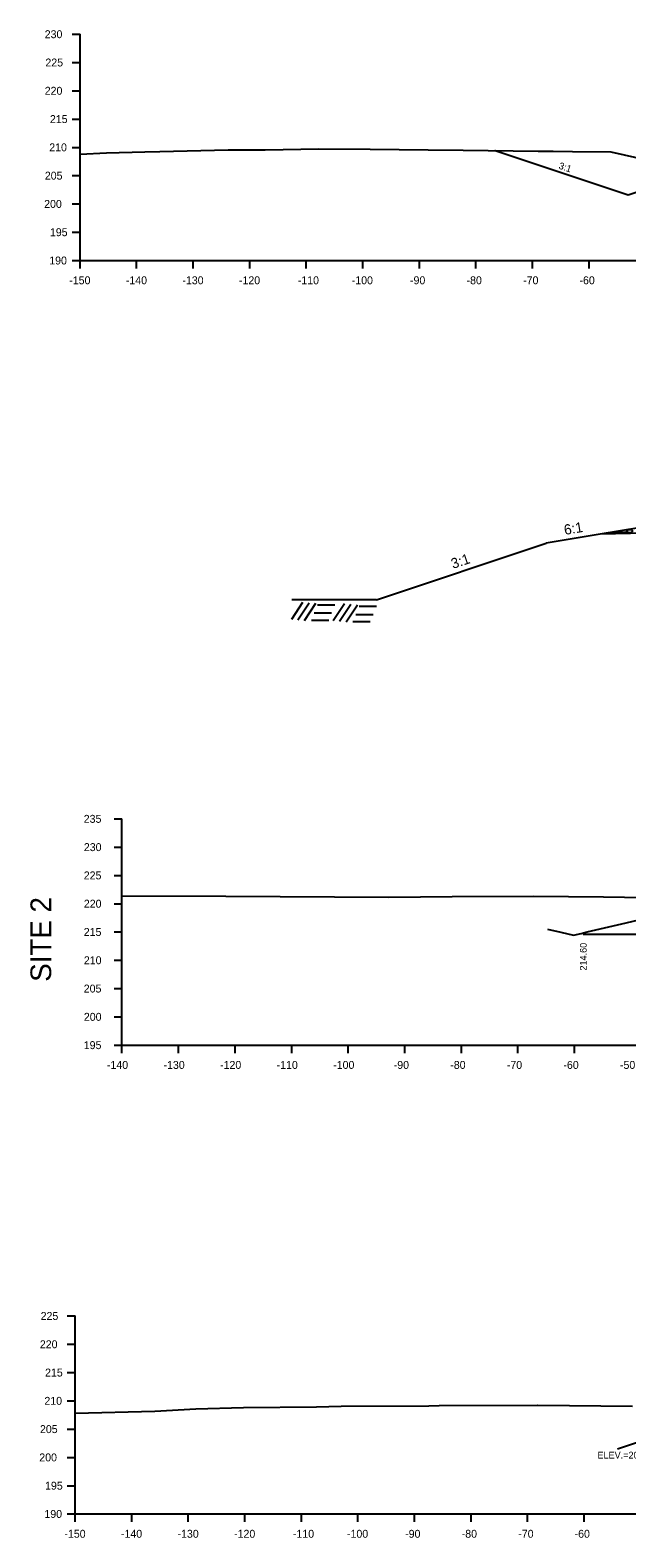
# Model space of a CAD drawing. Extents: x 2829243 to 2838161, y 467639 to 474695.
# Drawn here: x 2831378 to 2831905, y 468841 to 470174 of the extents above; entities that cross this region are included whole.
import ezdxf

# ---------------------------------------------------------------- set-up
doc = ezdxf.new("R2010")
doc.units = 0
for name, color, linetype in [('R_Axis', 7, 'Continuous'), ('R_Axis Annot', 7, 'Continuous'), ('R_Dimension', 7, 'Continuous'), ('R_Draft', 7, 'Continuous'), ('R_Exist Surface', 7, 'Continuous'), ('R_Fin Surface', 7, 'Continuous'), ('R_Grid', 7, 'Continuous'), ('R_Water', 7, 'Continuous'), ('R_Xsect Elev', 7, 'Continuous'), ('R_Xsect Slope', 7, 'Continuous')]:
    doc.layers.add(name, color=color, linetype=linetype)

msp = doc.modelspace()

# ---------------------------------------------------------------- linework, layer by layer
at = {"layer": 'R_Axis'}
for p, q in [((2831415, 470170.3), (2831422, 470170.3)), ((2831422, 469970.3), (2831422, 470170.3)), ((2831415, 470145.3), (2831422, 470145.3)), ((2831415, 470120.3), (2831422, 470120.3)), ((2831415, 470095.3), (2831422, 470095.3)), ((2831415, 470070.3), (2831422, 470070.3)), ((2831415, 470045.3), (2831422, 470045.3)), ((2831415, 470020.3), (2831422, 470020.3)), ((2831415, 469995.3), (2831422, 469995.3)), ((2831415, 469970.3), (2831422, 469970.3)), ((2831422, 469970.3), (2832922, 469970.3)), ((2831422, 469963.3), (2831422, 469970.3)), ((2831472, 469963.3), (2831472, 469970.3)), ((2831522, 469963.3), (2831522, 469970.3)), ((2831572, 469963.3), (2831572, 469970.3)), ((2831622, 469963.3), (2831622, 469970.3)), ((2831672, 469963.3), (2831672, 469970.3)), ((2831722, 469963.3), (2831722, 469970.3)), ((2831772, 469963.3), (2831772, 469970.3)), ((2831822, 469963.3), (2831822, 469970.3)), ((2831872, 469963.3), (2831872, 469970.3)), ((2831452.1, 469476.8), (2831459.1, 469476.8)), ((2831459.1, 469276.8), (2831459.1, 469476.8)), ((2831452.1, 469451.8), (2831459.1, 469451.8)), ((2831452.1, 469426.8), (2831459.1, 469426.8)), ((2831452.1, 469401.8), (2831459.1, 469401.8)), ((2831452.1, 469376.8), (2831459.1, 469376.8)), ((2831452.1, 469351.8), (2831459.1, 469351.8)), ((2831452.1, 469326.8), (2831459.1, 469326.8)), ((2831452.1, 469301.8), (2831459.1, 469301.8)), ((2831452.1, 469276.8), (2831459.1, 469276.8)), ((2831459.1, 469276.8), (2832859.1, 469276.8)), ((2831459.1, 469269.8), (2831459.1, 469276.8)), ((2831509.1, 469269.8), (2831509.1, 469276.8)), ((2831559.1, 469269.8), (2831559.1, 469276.8)), ((2831609.1, 469269.8), (2831609.1, 469276.8)), ((2831659.1, 469269.8), (2831659.1, 469276.8)), ((2831709.1, 469269.8), (2831709.1, 469276.8)), ((2831759.1, 469269.8), (2831759.1, 469276.8)), ((2831809.1, 469269.8), (2831809.1, 469276.8)), ((2831859.1, 469269.8), (2831859.1, 469276.8)), ((2831410.7, 469037.4), (2831417.7, 469037.4)), ((2831417.7, 468862.4), (2831417.7, 469037.4)), ((2831410.7, 469012.4), (2831417.7, 469012.4)), ((2831410.7, 468987.4), (2831417.7, 468987.4)), ((2831410.7, 468962.4), (2831417.7, 468962.4)), ((2831410.7, 468937.4), (2831417.7, 468937.4)), ((2831410.7, 468912.4), (2831417.7, 468912.4)), ((2831410.7, 468887.4), (2831417.7, 468887.4)), ((2831410.7, 468862.4), (2831417.7, 468862.4)), ((2831417.7, 468862.4), (2832917.7, 468862.4)), ((2831417.7, 468855.4), (2831417.7, 468862.4)), ((2831467.7, 468855.4), (2831467.7, 468862.4)), ((2831517.7, 468855.4), (2831517.7, 468862.4)), ((2831567.7, 468855.4), (2831567.7, 468862.4)), ((2831617.7, 468855.4), (2831617.7, 468862.4)), ((2831667.7, 468855.4), (2831667.7, 468862.4)), ((2831717.7, 468855.4), (2831717.7, 468862.4)), ((2831767.7, 468855.4), (2831767.7, 468862.4)), ((2831817.7, 468855.4), (2831817.7, 468862.4)), ((2831867.7, 468855.4), (2831867.7, 468862.4))]:
    msp.add_line(p, q, dxfattribs=at)
at = {"layer": 'R_Draft'}
for p, q in [((2831984.1, 469745.4), (2831881.8, 469728.4)), ((2831881.8, 469728.4), (2831834.1, 469720.4)), ((2832209.1, 469734.9), (2831881.8, 469728.4)), ((2831684.1, 469670.4), (2831834.1, 469720.4)), ((2831684.1, 469670.4), (2831609.1, 469670.4)), ((2831609.1, 469653.3), (2831619.1, 469668.4)), ((2831614.5, 469652.7), (2831624.5, 469667.8)), ((2831620.5, 469652.2), (2831630.5, 469667.3)), ((2831629.1, 469658.9), (2831644.3, 469658.9)), ((2831632, 469666.1), (2831647.3, 469666.1)), ((2831645.9, 469652), (2831655.9, 469667.1)), ((2831651.3, 469651.4), (2831661.3, 469666.5)), ((2831657.3, 469650.8), (2831667.3, 469665.9)), ((2831665.9, 469657.5), (2831681.1, 469657.5)), ((2831668.8, 469664.8), (2831684.1, 469664.8)), ((2831626.5, 469652.5), (2831641.8, 469652.5)), ((2831663.3, 469651.1), (2831678.6, 469651.1))]:
    msp.add_line(p, q, dxfattribs=at)
for points in [[(2831885.3, 469728.4), (2831885.3, 469728.4), (2831885.3, 469728.5), (2831885.3, 469728.7), (2831885.3, 469728.8), (2831885.3, 469728.9), (2831885.3, 469728.9)], [(2831885.4, 469728.9), (2831885.4, 469728.9), (2831885.4, 469728.8), (2831885.3, 469728.7), (2831885.4, 469728.6), (2831885.4, 469728.5), (2831885.4, 469728.4)], [(2831890.3, 469728.5), (2831890.3, 469728.6), (2831890.3, 469728.7), (2831890.3, 469728.9), (2831890.3, 469729.1), (2831890.2, 469729.3), (2831890, 469729.4), (2831889.8, 469729.5), (2831889.7, 469729.6), (2831889.6, 469729.6), (2831889.6, 469729.6)], [(2831890.5, 469729.2), (2831890.5, 469729.2), (2831890.4, 469729), (2831890.4, 469728.9), (2831890.3, 469728.7), (2831890.4, 469728.6), (2831890.4, 469728.5), (2831890.4, 469728.5)], [(2831895.3, 469728.6), (2831895.3, 469728.6), (2831895.3, 469728.7), (2831895.3, 469728.9), (2831895.3, 469729.1), (2831895.2, 469729.3), (2831895, 469729.4), (2831894.8, 469729.5), (2831894.7, 469729.6), (2831894.4, 469729.7), (2831894.1, 469729.9), (2831893.6, 469729.9), (2831893.1, 469729.9), (2831892.6, 469729.9), (2831892.2, 469729.9), (2831891.8, 469729.8), (2831891.5, 469729.7), (2831891.1, 469729.6), (2831890.9, 469729.4), (2831890.7, 469729.3), (2831890.5, 469729.2), (2831890.5, 469729.1)], [(2831891.9, 469730), (2831892.1, 469730), (2831892.5, 469729.9), (2831893.1, 469729.9), (2831893.9, 469730), (2831894.5, 469730.2), (2831894.8, 469730.4), (2831895, 469730.5)], [(2831895.5, 469729.2), (2831895.5, 469729.2), (2831895.4, 469729), (2831895.4, 469728.9), (2831895.3, 469728.7), (2831895.4, 469728.6), (2831895.4, 469728.6)], [(2831900.3, 469728.7), (2831900.4, 469728.8), (2831900.3, 469728.9), (2831900.3, 469729.1), (2831900.2, 469729.3), (2831900, 469729.4), (2831899.8, 469729.5), (2831899.7, 469729.6), (2831899.4, 469729.7), (2831899.1, 469729.9), (2831898.6, 469729.9), (2831898.1, 469729.9), (2831897.6, 469729.9), (2831897.2, 469729.9), (2831896.8, 469729.8), (2831896.5, 469729.7), (2831896.2, 469729.6), (2831895.9, 469729.4), (2831895.7, 469729.3), (2831895.5, 469729.2), (2831895.5, 469729.1)], [(2831895.6, 469730.6), (2831895.7, 469730.6), (2831895.8, 469730.5), (2831895.9, 469730.4), (2831896.1, 469730.3), (2831896.4, 469730.2), (2831896.8, 469730), (2831897.4, 469729.9), (2831898.1, 469729.9), (2831898.9, 469730), (2831899.6, 469730.2), (2831900, 469730.6), (2831900.3, 469730.8), (2831900.3, 469731.1), (2831900.4, 469731.3), (2831900.3, 469731.4), (2831900.3, 469731.4)], [(2831900.4, 469731.5), (2831900.4, 469731.4), (2831900.4, 469731.3), (2831900.3, 469731.2), (2831900.4, 469731), (2831900.5, 469730.8), (2831900.6, 469730.6), (2831900.8, 469730.5), (2831900.9, 469730.4), (2831901.1, 469730.3), (2831901.4, 469730.2), (2831901.8, 469730), (2831902.4, 469729.9), (2831903.2, 469729.9), (2831903.9, 469730), (2831904.6, 469730.2), (2831905, 469730.6), (2831905.3, 469730.8), (2831905.4, 469731.1), (2831905.4, 469731.4), (2831905.3, 469731.6), (2831905.2, 469731.7), (2831905, 469731.8), (2831904.9, 469731.9), (2831904.7, 469732.1), (2831904.6, 469732.1), (2831904.5, 469732.1)], [(2831900.6, 469729.2), (2831900.5, 469729.2), (2831900.4, 469729), (2831900.4, 469728.9), (2831900.4, 469728.8), (2831900.4, 469728.7)], [(2831905.4, 469728.8), (2831905.4, 469728.9), (2831905.3, 469729), (2831905.3, 469729.1), (2831905.2, 469729.3), (2831905, 469729.4), (2831904.9, 469729.5), (2831904.7, 469729.6), (2831904.4, 469729.7), (2831904.1, 469729.9), (2831903.6, 469729.9), (2831903.1, 469729.9), (2831902.6, 469729.9), (2831902.2, 469729.9), (2831901.8, 469729.8), (2831901.5, 469729.7), (2831901.2, 469729.6), (2831900.9, 469729.4), (2831900.7, 469729.3), (2831900.5, 469729.2), (2831900.5, 469729.1)], [(2831905.6, 469731.6), (2831905.5, 469731.6), (2831905.5, 469731.5), (2831905.4, 469731.3), (2831905.3, 469731.2), (2831905.4, 469731), (2831905.5, 469730.8), (2831905.6, 469730.6), (2831905.8, 469730.5), (2831905.9, 469730.4), (2831906.1, 469730.3), (2831906.4, 469730.2), (2831906.8, 469730), (2831907.5, 469729.9), (2831908.2, 469729.9), (2831908.9, 469730), (2831909.6, 469730.2), (2831910, 469730.6), (2831910.3, 469730.8), (2831910.4, 469731.1), (2831910.4, 469731.4), (2831910.3, 469731.6), (2831910.2, 469731.7), (2831910.1, 469731.8), (2831909.9, 469731.9), (2831909.7, 469732.1), (2831909.5, 469732.2), (2831909.1, 469732.3), (2831908.7, 469732.3), (2831908.1, 469732.4), (2831907.6, 469732.3), (2831907.2, 469732.3), (2831906.8, 469732.2), (2831906.5, 469732.2), (2831906.2, 469732), (2831905.9, 469731.9), (2831905.7, 469731.7), (2831905.6, 469731.6), (2831905.5, 469731.6)]]:
    msp.add_open_spline(points, degree=3, dxfattribs=at)
at = {"layer": 'R_Exist Surface'}
for points in [[(2831422, 470064.3), (2831445.4, 470065.4), (2831479.2, 470066.2), (2831492.7, 470066.6), (2831553, 470068.2), (2831585.8, 470068), (2831633, 470068.9), (2831678.5, 470068.6), (2831729.8, 470068), (2831760.6, 470067.8), (2831827, 470067), (2831840.3, 470066.9), (2831857.2, 470066.7), (2831891.2, 470066.2), (2831923.9, 470058.9)], [(2831459.1, 469408.9), (2831551, 469408.4), (2831694.9, 469407.7), (2831751, 469408.1), (2831822.9, 469408.4), (2831884.6, 469408), (2832015.7, 469405.7)], [(2831417.7, 468951.4), (2831488.1, 468953.4), (2831524.3, 468955.3), (2831566.5, 468956.6), (2831631.1, 468957.1), (2831652.9, 468957.8), (2831730.3, 468958.1), (2831739.5, 468958.3), (2831826.3, 468958.5), (2831826.4, 468958.5), (2831826.6, 468958.5), (2831910.3, 468957.8)]]:
    msp.add_lwpolyline(points, dxfattribs=at)
at = {"layer": 'R_Fin Surface'}
for points in [[(2831789.1, 470067.5), (2831789.1, 470067.5), (2831906.6, 470028.3), (2832047, 470075.1), (2832062.7, 470077.7), (2832097, 470083.4), (2832117, 470084.2), (2832165.2, 470085.2), (2832172, 470085.3), (2832179.9, 470085.2), (2832227, 470084.2), (2832237.4, 470083.8), (2832247, 470083.4), (2832281.2, 470077.7), (2832312, 470072.6), (2832389.6, 470071)], [(2831835.1, 469379.4), (2831847, 469376.7), (2831858.3, 469374), (2831865.1, 469375.6), (2831870.4, 469376.9), (2831904.7, 469384.9), (2831941.1, 469393.4), (2831944.2, 469394.2), (2831948.2, 469395.1), (2831979.4, 469400.6), (2832063, 469415.3)], [(2831897.2, 468920), (2832032.7, 468965.2), (2832042.9, 468966.9), (2832092.7, 468975.2)]]:
    msp.add_lwpolyline(points, dxfattribs=at)
at = {"layer": 'R_Grid'}
for p, q in [((2831459.1, 469276.8), (2831459.1, 469476.8)), ((2831459.1, 469276.8), (2832859.1, 469276.8)), ((2831417.7, 468862.4), (2831417.7, 469037.4)), ((2831417.7, 468862.4), (2832917.7, 468862.4))]:
    msp.add_line(p, q, dxfattribs=at)
at = {"layer": 'R_Water'}
msp.add_line((2831866.9, 469374.8), (2832472.3, 469374.3), dxfattribs=at)

# ---------------------------------------------------------------- texts
at = {"layer": 'R_Axis Annot'}
for s, p in [('230', (2831390.8, 470166.8)), ('225', (2831391.4, 470141.8)), ('220', (2831390.8, 470116.8)), ('215', (2831395.4, 470091.8)), ('210', (2831394.8, 470066.8)), ('205', (2831390.9, 470041.8)), ('200', (2831390.3, 470016.8)), ('195', (2831395.4, 469991.8)), ('190', (2831394.8, 469966.8)), ('-150', (2831412.5, 469949.3)), ('-140', (2831462.5, 469949.3)), ('-130', (2831512.5, 469949.3)), ('-120', (2831562.5, 469949.3)), ('-110', (2831614.5, 469949.3)), ('-100', (2831662.2, 469949.3)), ('-90', (2831713.7, 469949.3)), ('-80', (2831763.7, 469949.3)), ('-70', (2831813.7, 469949.3)), ('-60', (2831863.5, 469949.3)), ('235', (2831425.3, 469473.3)), ('230', (2831425.4, 469448.3)), ('225', (2831425.3, 469423.3)), ('220', (2831425.4, 469398.3)), ('215', (2831425.3, 469373.3)), ('210', (2831425.4, 469348.3)), ('205', (2831425.3, 469323.3)), ('200', (2831425.4, 469298.3)), ('195', (2831425.3, 469273.3)), ('-140', (2831445.8, 469255.8)), ('-130', (2831495.8, 469255.8)), ('-120', (2831545.8, 469255.8)), ('-110', (2831595.8, 469255.8)), ('-100', (2831645.8, 469255.8)), ('-90', (2831699.3, 469255.8)), ('-80', (2831749.3, 469255.8)), ('-70', (2831799.3, 469255.8)), ('-60', (2831849.3, 469255.8)), ('-50', (2831899.3, 469255.8)), ('225', (2831387.2, 469033.9)), ('220', (2831386.5, 469008.9)), ('215', (2831391.1, 468983.9)), ('210', (2831390.5, 468958.9)), ('205', (2831386.6, 468933.9)), ('200', (2831386, 468908.9)), ('195', (2831391.1, 468883.9)), ('190', (2831390.5, 468858.9)), ('-150', (2831408.2, 468841.4)), ('-140', (2831458.2, 468841.4)), ('-130', (2831508.2, 468841.4)), ('-120', (2831558.2, 468841.4)), ('-110', (2831610.2, 468841.4)), ('-100', (2831658, 468841.4)), ('-90', (2831709.4, 468841.4)), ('-80', (2831759.4, 468841.4)), ('-70', (2831809.4, 468841.4)), ('-60', (2831859.2, 468841.4))]:
    msp.add_text(s, height=7, dxfattribs=at).set_placement(p)
at = {"layer": 'R_Dimension'}
msp.add_text('SITE 2', height=18.31, rotation=90, dxfattribs=at).set_placement((2831396.5, 469332.8))
at = {"layer": 'R_Draft'}
for s, rotation, p in [('6:1', 9.4623, (2831850.6, 469727.7)), ('3:1', 18.4349, (2831751.7, 469697.7))]:
    msp.add_text(s, height=9, rotation=rotation, dxfattribs=at).set_placement(p)
at = {"layer": 'R_Xsect Elev'}
msp.add_text('214.60', height=6, rotation=90, dxfattribs=at).set_placement((2831869.9, 469342.7))
msp.add_text('ELEV.=201.60', height=6, dxfattribs=at).set_placement((2831879.4, 468911.4))
at = {"layer": 'R_Xsect Slope'}
msp.add_text('3:1', height=6, rotation=341.5662, dxfattribs=at).set_placement((2831844.7, 470051.6))

doc.saveas('drawing.dxf')
